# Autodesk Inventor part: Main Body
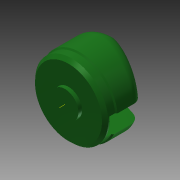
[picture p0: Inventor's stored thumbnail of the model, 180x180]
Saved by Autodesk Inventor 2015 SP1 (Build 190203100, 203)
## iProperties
Created: 2008-11
Part Number: Main Body
Document SubType Name: Modeling
Designer: dwoollam
Density: 7.85 g/cm^3
Material: Steel
Appearance: Smooth - Dark Forest Green
Mass: 1.3224e+07 g
Surface Area: 122861 cm^2
Volume: 1.68458e+06 cm^3
Dwg_Category: Clearance_Mewp
INSTALLATION: False
CIVIL_WORK: False
EARTHING: False
MOUNTING: False
Author: dwoollam
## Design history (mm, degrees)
sketch "Sketch1"
  geometry: L1 (0, 1200)-(0, 0); L2 (0, 0)-(780, 0); L3 (780, 0)-(850, 75); L4 (850, 75)-(850, 240); L5 (850, 240)-(880, 265); L6 (880, 265)-(880, 1085); L7 (880, 1085)-(0, 1085); L8 (0, 0)-(315, 0); L9 (315, 0)-(315, -84.5); L10 (315, -84.5)-(0, -84.5); L11 (0, -84.5)-(0, 0); L12 (-42.29, 1110)-(957.71, 1110); L13 (957.71, 1110)-(957.71, 794.701); L14 (957.71, 794.701)-(-42.29, 1110); L15 (37, 1085)-(37, 1110); C1 r 30 at (-675, 430); 2 further points
  constraints: 30 end point, 7 perpendicular, 5 point on line, 3 parallel, 1 centre point, 1 coincident, 1 horizontal, 1 vertical
  dimensions: "d0" = 1200 distance of L1.start L1.end; "d3" = 30 distance between parallel lines of L6 L4; "d4" = 70 distance from line of L2.end L4; "d5" = 75 distance from line of L3.end L2; "d6" = 165 distance of L3.end L4.end; "d7" = 25 vertical distance of L4.end L5.end; "d9" = 1085 distance between parallel lines of L7 L2; "d10" = 1760 diameter of L6 L1; "d12" = 84.5 distance of L8.end L9.end; "d13" = 315 distance of L9.end L10.end; "d14" = 17.5 deg angle of L12 L14; "d15" = 25 distance between parallel lines of L7 L12; "d17" = 37 distance of L7.end L15.start; "d18" = 1000 distance of L12.start L12.end; "d28" = 60 diameter of C1; "d29" = 675 horizontal distance of point (0, 0) C1.centre; "d40" = 430 vertical distance of C1.centre point (0, 0)
revolve "Main Body" stored, may be unused: angle "d11" = 90 deg
extrude "Main Body_Sub1" cut sketch "Sketch1" stored distance "d19" = 1760; taper "d20" = 0 deg
fillet "Fillet1" dims "d21" = 250
sketch "Sketch2"
  geometry: L1 (900, 380)-(-900, 380); L2 (-900, 380)-(-900, -85); L3 (-900, -85)-(900, -85); L4 (900, -85)-(900, 380); A1 r 630 centre (0, 0) between (-1.479, 629.998) and (-1.479, -629.998) reference
  constraints: 8 end point, 2 parallel, 1 horizontal, 1 perpendicular
  dimensions: "d22" = 900 distance from line of A1.centre L2; "d23" = 465 distance of L3.end L1.start; "d24" = 380 distance from line of L1 A1.centre; "d25" = 1800 distance of L1.start L1.end
extrude "Main Body_Sub2" cut sketch "Sketch2" distance "d26" = 980; taper "d27" = 0 deg
extrude "Hole_Pivot1" cut sketch "Sketch1" stored distance "d32" = 1750; taper "d33" = 0 deg
workaxis "Work Axis1"
sketch "Sketch5"
  geometry: L1 (-793.725, 265)-(-793.725, 835) reference; L2 (-775, 685)-(-614.378, 685); L3 (-718.301, 505)-(-775, 505); L4 (-775, 505)-(-775, 685); L5 (-718.301, 505)-(-614.378, 685); C1 r 30 at (-675, 430) reference; 1 further point
  constraints: 8 end point, 1 horizontal, 1 parallel, 1 vertical
  dimensions: "d41" = 75 distance from line of C1.centre L3; "d42" = 180 distance between parallel lines of L3 L2; "d43" = 120 deg angle of L3 L5; "d44" = 75 distance from line of L5 C1.centre; "d54" = 18.725 distance between parallel lines of L1 L4
extrude "Stop_No1" join sketch "Sketch5" stored distance "d46" = 760; taper "d47" = 0 deg
sketch "Sketch6"
  geometry: L1 (622.761, 0)-(0, 0) reference; L2 (622.761, 0)-(622.761, -544.998) reference; L3 (282.761, -80)-(-267.239, -80); L4 (-267.239, -80)-(-267.239, 535); L5 (-267.239, 535)-(282.761, 535); L6 (282.761, 535)-(282.761, -80); L7 (121.746, 465)-(622.761, 465) reference
  constraints: 8 end point, 2 parallel, 1 horizontal, 1 perpendicular
  dimensions: "d48" = 80 distance between parallel lines of L3 L1; "d49" = 340 distance between parallel lines of L6 L2; "d50" = 550 distance of L3.start L3.end; "d51" = 70 distance from line of L7.start L5
extrude "Stop_No2" cut sketch "Sketch6" distance "d52" = 410; taper "d53" = 0 deg
body "Solid1"
